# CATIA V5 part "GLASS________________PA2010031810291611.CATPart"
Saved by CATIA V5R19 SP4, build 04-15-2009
Part number: GLASS________________PA2010031810291611
Bounding box of the stored display mesh (mm): x -17.65 to 17.65, y -19.44 to -18.64, z -5.65 to 5.65
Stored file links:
  E:\CadInnWork\1\GLASS________________PA2010031810291611.CATPart
  C:\Documents and Settings\moren\Bureau\3D models\Lampe\CATIA_V5\pocket_lamp.CATProduct
  C:\Documents and Settings\moren\Bureau\3D models\Lampe\CATIA_V5\plastic_housing_bottom.CATPart
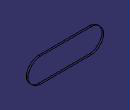
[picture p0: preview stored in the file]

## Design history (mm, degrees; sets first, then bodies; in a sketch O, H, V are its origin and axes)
Parameters
  Update = false
  PDM_version = "A"
  PDM_iteration = 1
  PDM_owner = "moren                    "
  PDM_comment = ""
  PDM_partnumber = "PA002170EA6A57201003181029160011"
Set1
  DatumSurface1: linked copy from another document
  DatumCurve1 to DatumCurve3: linked copy from another document
Body1 (main body)
  Sketch1 on face of DatumSurface1, origin (0, -18.64, 0), H (-1, 0, 0), V (0, 0, 1)
    offset curve E4 from edge of DatumCurve1
    offset line E5 (-12, -5.65) -> (12, -5.65) from edge of DatumCurve2
    offset curve E6 from edge of DatumCurve3
    line L1 (-17.65, 0) -> (17.65, 0)
    horizontal: L1 H
  Pad1: profile Sketch1, direction (0, -1, 0), length 0.8
  Mirror1: of the body so far, about xy-plane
